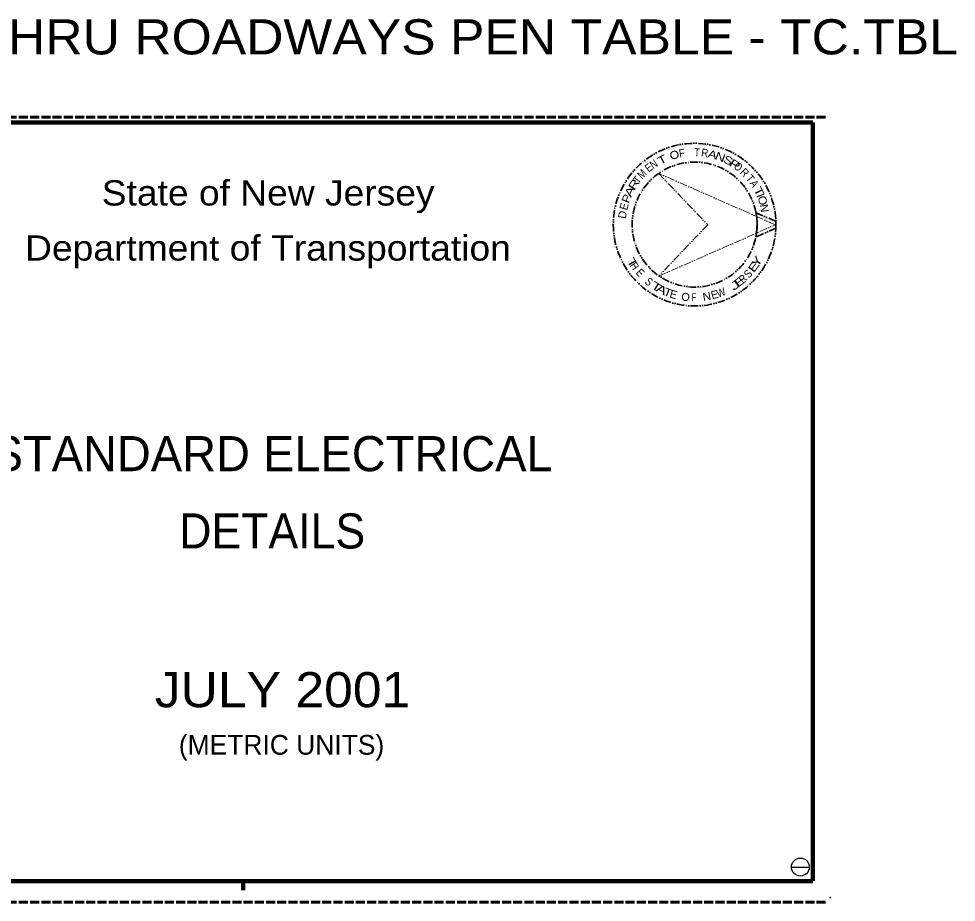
# Model space of a CAD drawing. Extents: x 312912 to 313215, y 317800 to 318182.
# Drawn here: x 313015 to 313215.2, y 317993.5 to 318182.1 of the extents above; entities that cross this region are included whole.
import ezdxf
from ezdxf.enums import TextEntityAlignment as Align

# ---------------------------------------------------------------- set-up
doc = ezdxf.new("R2010")
doc.units = 0
doc.header["$LTSCALE"] = 0.32
doc.header["$PDMODE"] = 32
doc.header["$PDSIZE"] = 0.16
doc.linetypes.add('DASH_DOUBLE_DOT', pattern=[9.2, 5, -1.2, 0.3, -1.2, 0.3, -1.2])
doc.linetypes.add('LONG_DASHED', pattern=[7.5, 6, -1.5])
for name, color, linetype, lineweight in [('1', 7, 'Continuous', 13), ('10', 7, 'Continuous', 25), ('60', 7, 'DASH_DOUBLE_DOT', 35), ('63', 7, 'LONG_DASHED', 60)]:
    doc.layers.add(name, color=color, linetype=linetype, lineweight=lineweight)

msp = doc.modelspace()

# ---------------------------------------------------------------- linework, layer by layer
at = {"layer": '1', "lineweight": 158}
for p, q in [((313184.5648, 317998.047), (313184.5648, 318159.987)), ((312952.0648, 317997.987), (313184.5648, 317997.987)), ((313062.9148, 317996.067), (313062.9148, 317997.987))]:
    msp.add_line(p, q, dxfattribs=at)
msp.add_lwpolyline([(312952.0648, 317998.047), (312952.0648, 318159.987), (313184.5648, 318159.987)], dxfattribs=at)
at = {"layer": '1'}
msp.add_point((313188.3148, 317994.487), dxfattribs=at)
at = {"layer": '10'}
msp.add_line((313180.0032, 318000.9883), (313183.8442, 318000.9883), dxfattribs=at)
msp.add_circle((313181.9142, 318001.0029), 1.9159, dxfattribs=at)
at = {"layer": '60', "lineweight": 13}
msp.add_lwpolyline([(313151.6548, 318127.167), (313176.5848, 318138.147), (313151.6548, 318149.127), (313162.1248, 318138.147)], close=True, dxfattribs=at)
at = {"layer": '60'}
msp.add_lwpolyline([(313172.4448, 318140.727), (313176.6748, 318138.867), (313176.7048, 318138.147), (313176.7048, 318137.457), (313172.4148, 318135.537), (313172.5348, 318136.347), (313172.6248, 318137.307), (313172.6548, 318138.687), (313172.5948, 318139.437)], close=True, dxfattribs=at)
for centre, radius in [((313159.3348, 318138.177), 17.37), ((313159.3288, 318138.1897), 13.3499)]:
    msp.add_circle(centre, radius, dxfattribs=at)
at = {"layer": '63'}
for p, q in [((313187.3148, 318161.127), (312919.0908, 318161.127)), ((313187.3148, 317993.487), (312919.0908, 317993.487))]:
    msp.add_line(p, q, dxfattribs=at)

# ---------------------------------------------------------------- texts
at = {"layer": '1'}
for s, height, width, p in [('RUN THIS SHEET THRU ROADWAYS PEN TABLE - TC.TBL', 7.5, 1.1, (313063.2558, 318174.5267)), ('State of New Jersey', 5.4, 1.1, (313068.239, 318142.257)), ('Department of Transportation', 5.4, 1.1, (313068.1997, 318130.497)), ('DETAILS', 7.5, 0.95, (313069.1056, 318069.0269)), ('JULY 2001', 7.5, 1.1, (313071.305, 318035.127))]:
    msp.add_text(s, height=height, dxfattribs=dict(at, width=width)).set_placement(p, align=Align.CENTER)
for s, rotation, width, p in [('T', 27.018, 1.4, (313152.8006, 318151.2683)), ('O', 14.996, 1.15, (313155.2388, 318152.2379)), ('F', 8.996, 0.9, (313156.7467, 318152.6154)), ('T', 356.972, 0.8, (313159.8025, 318152.7875)), ('R', 350.972, 0.9, (313161.3696, 318152.6687)), ('A', 344.972, 1.25, (313162.9345, 318152.3355)), ('N', 338.974, 1.3, (313164.5077, 318151.8315)), ('S', 332.976, 1.25, (313166.103, 318151.1493)), ('E', 39.018, 0.85, (313150.061, 318149.6872)), ('N', 33.017, 0.85, (313151.0515, 318150.3848)), ('P', 326.975, 1.5, (313167.4637, 318150.3037)), ('O', 320.973, 0.85, (313168.1166, 318149.8773)), ('T', 51.016, 0.85, (313147.7369, 318147.2168)), ('M', 45.018, 0.85, (313148.6659, 318148.3884)), ('R', 314.977, 0.85, (313169.4378, 318148.7136)), ('T', 308.978, 0.85, (313170.5368, 318147.4973)), ('R', 57.015, 1.4, (313147.0734, 318146.3009)), ('A', 302.976, 0.85, (313171.3594, 318146.4504)), ('P', 69.016, 1.2, (313145.5927, 318143.4419)), ('A', 63.016, 1.5, (313146.231, 318144.8608)), ('T', 296.975, 1.4, (313172.305, 318144.8618)), ('E', 75.012, 0.95, (313145.0919, 318141.8457)), ('O', 284.978, 1.15, (313173.0354, 318143.1131)), ('N', 278.979, 1.05, (313173.3923, 318141.5366)), ('T', 300.466, 1.5, (313145.3001, 318129.621)), ('Y', 59.155, 1.5, (313173.3829, 318129.875)), ('H', 305.99, 0.85, (313145.8031, 318128.841)), ('E', 311.505, 0.85, (313147.0767, 318127.339)), ('E', 53.814, 1.5, (313172.6258, 318128.7006)), ('S', 322.102, 0.85, (313149.049, 318125.3267)), ('E', 37.563, 1.5, (313169.4877, 318125.3791)), ('R', 42.838, 0.85, (313170.2068, 318126.001)), ('S', 48.172, 0.85, (313171.3794, 318127.1126)), ('T', 327.375, 1.55, (313150.7179, 318124.1953)), ('A', 332.946, 1.5, (313151.8888, 318123.5291)), ('T', 338.414, 1.25, (313153.2867, 318122.8937)), ('W', 21.219, 0.85, (313165.274, 318122.8845)), ('J', 37.654, 1.8, (313168.4802, 318124.5716)), ('F', 359.901, 0.7, (313159.1707, 318121.8261)), ('N', 10.652, 1.1, (313162.0861, 318122.0246))]:
    msp.add_text(s, height=1.71, rotation=rotation, dxfattribs=dict(at, width=width)).set_placement(p, align=Align.CENTER)
for s, rotation, p in [('I', 290.973, (313172.5677, 318144.1016)), ('D', 81.014, (313144.7641, 318140.1648)), ('E', 343.687, (313154.5893, 318122.4579)), ('O', 354.287, (313157.3154, 318121.8909)), ('E', 15.926, (313163.8249, 318122.4196))]:
    msp.add_text(s, height=1.71, rotation=rotation, dxfattribs=at).set_placement(p, align=Align.CENTER)
for s, height, p in [('STANDARD ELECTRICAL', 7.5, (313069.0948, 318085.527)), ('(METRIC UNITS)', 4.219, (313071.0991, 318024.995))]:
    msp.add_text(s, height=height, dxfattribs=at).set_placement(p, align=Align.CENTER)

doc.saveas('drawing.dxf')
